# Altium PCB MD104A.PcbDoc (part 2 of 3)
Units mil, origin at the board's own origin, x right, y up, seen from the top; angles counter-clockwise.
Board outline 3684 x 4279 mil, 4 copper layers (Top Layer, GND Layer, Power Layer, Bottom Layer), stack 61.2 mil thick; 215 components, 107 nets, 500 pads, 726 vias.
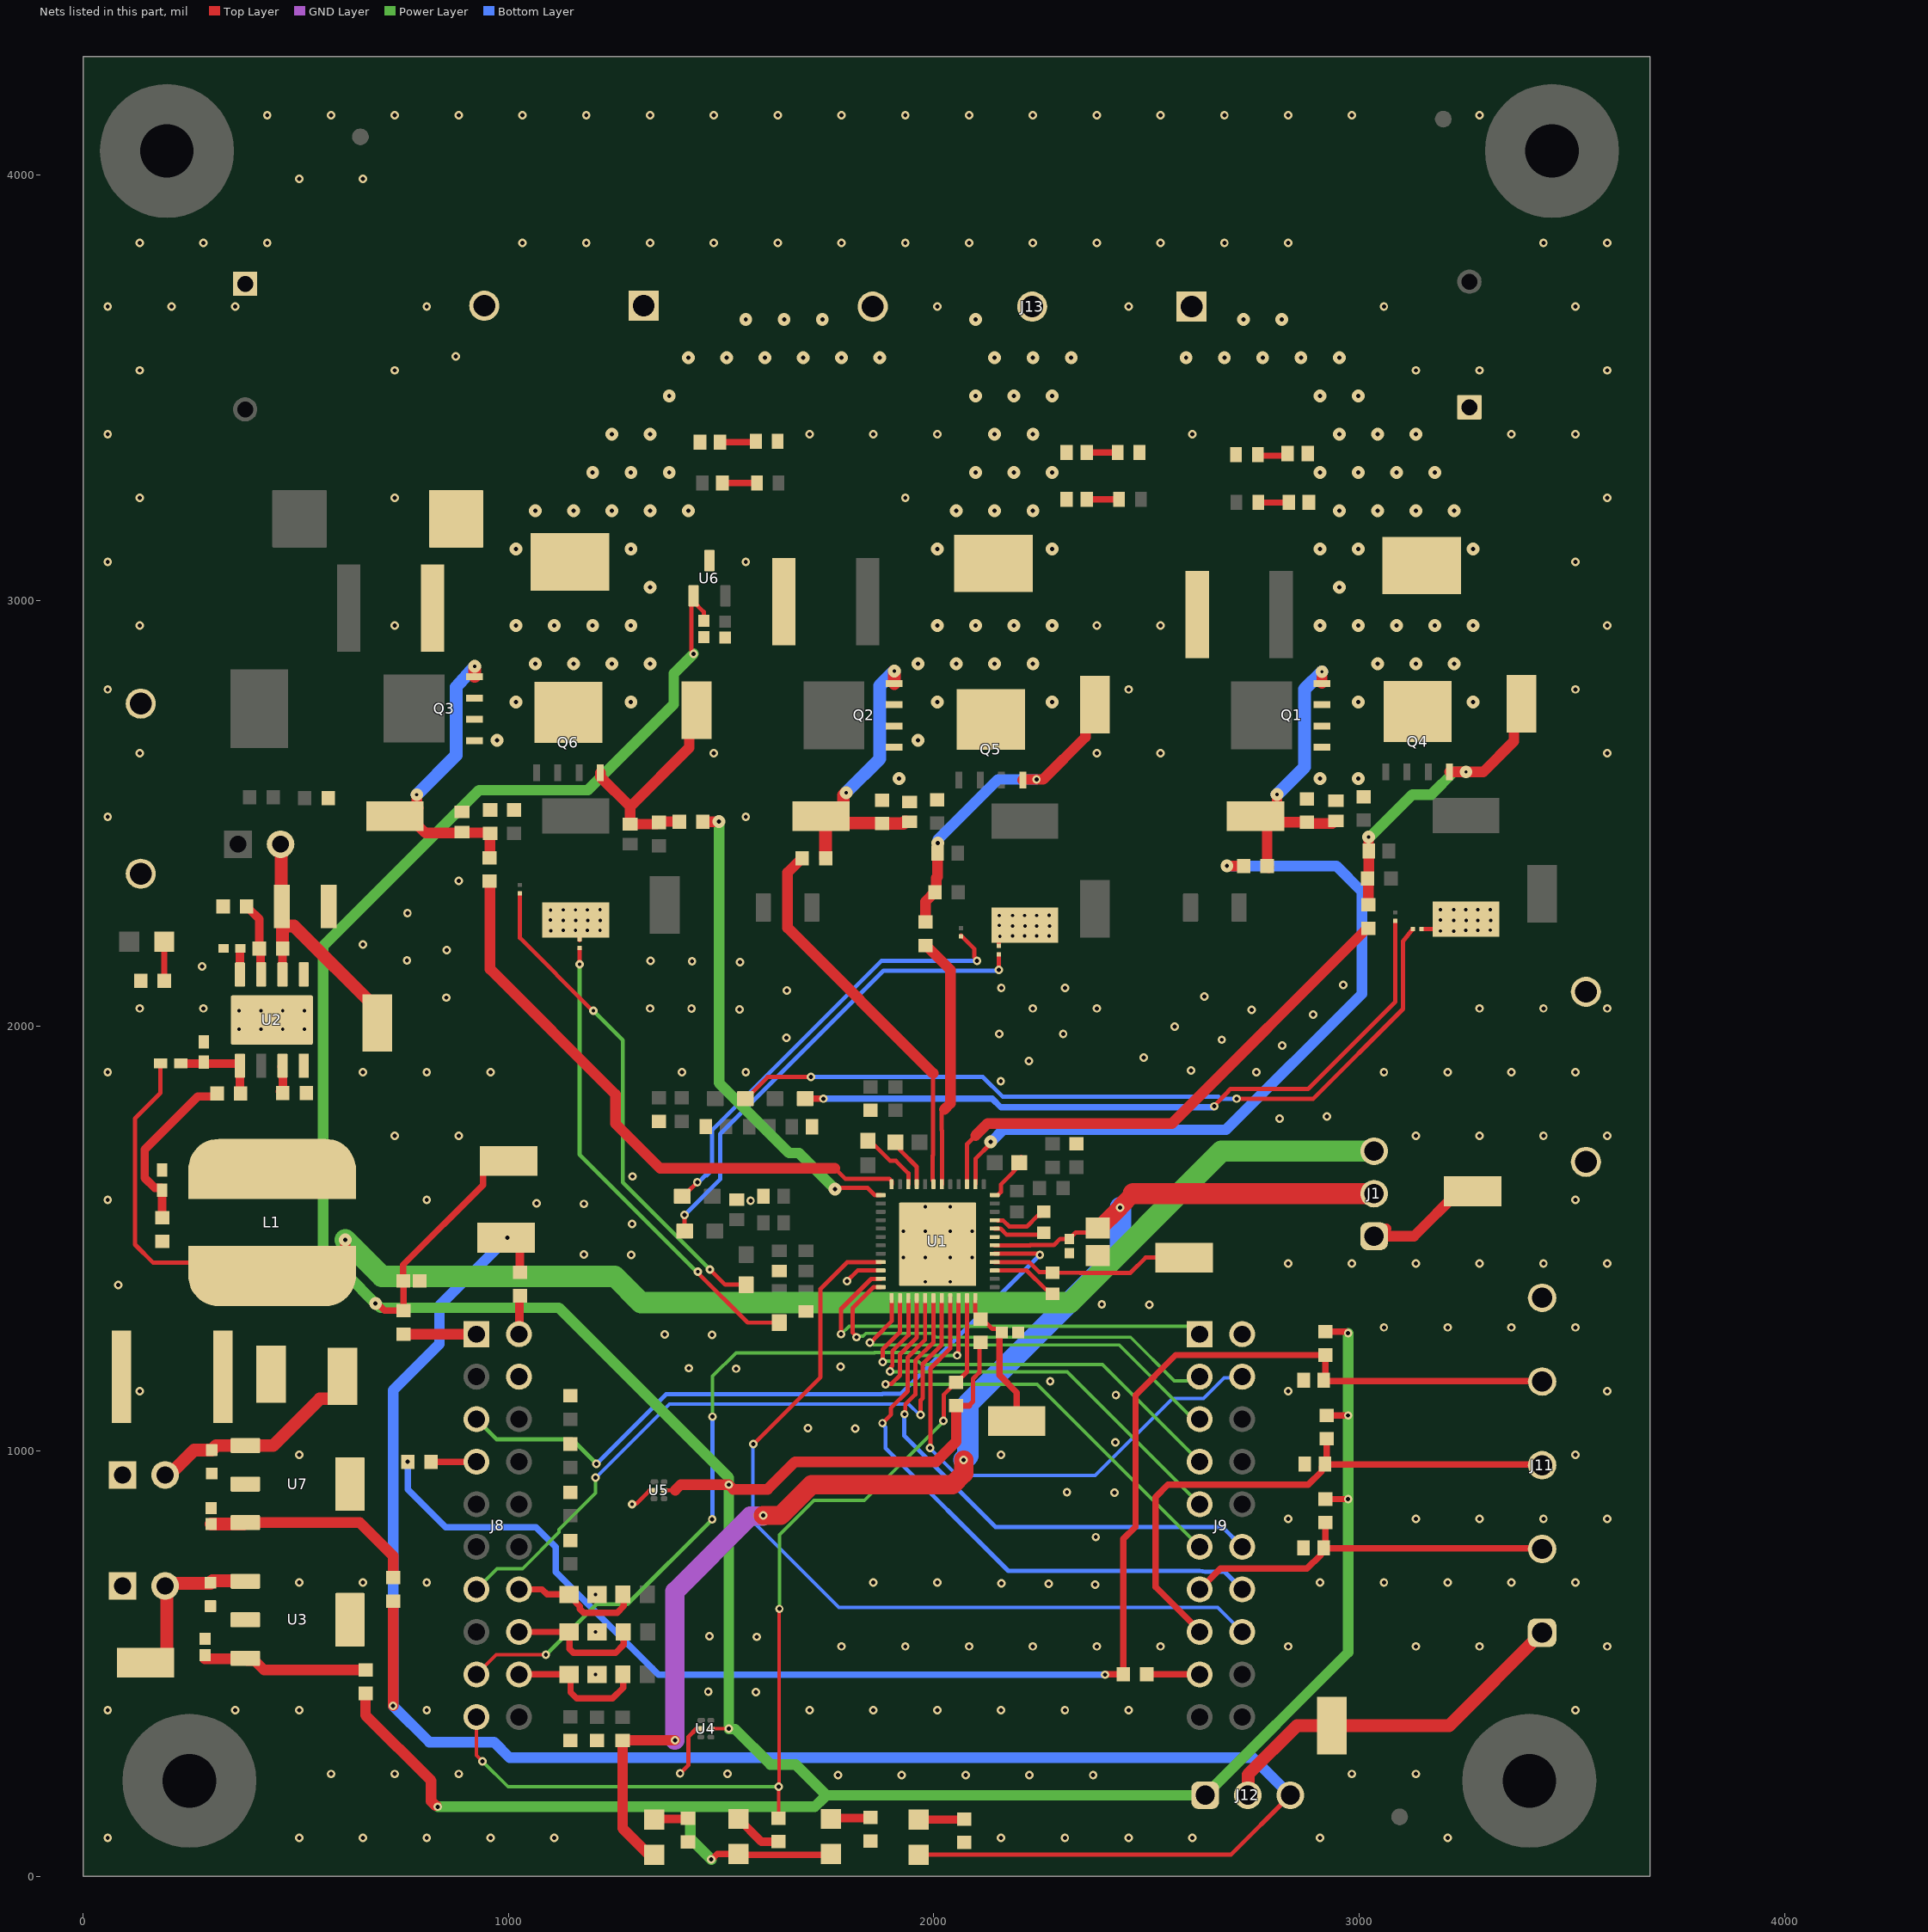
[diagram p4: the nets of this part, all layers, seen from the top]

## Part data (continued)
C10: library part CMP-06035-054272-1, "Ceramic Capacitor for Automotive 100nF ±10% 25VDC X7R 0402 Paper T/R", Capacitance=100nF, Case Code (Imperial)=0402, Case Code (Metric)=1005, Max Operating Temperature=125°C, Min Operating Temperature=-55°C, Ratings=AEC-Q200, Tolerance=10%, Voltage Rating=25V
C11 C22: library part CMP-0007085-4, "CAP, CERM, 2200 pF, 100 V, +/- 10%, X7R, AEC-Q200 Grade 1, 0603", Cap_Case=0603, Manufacturer=TDK, Supplier Part Number 1=445-5808-1-ND, TempCo=X7R, Tolerance_%=10%, Value1="0.923948 ohm", Value2=100V, ValueDisplayed=2200pF
C12 C13 C14 C15 C17 C19 C24 C25 C26 C27 C28 C29: library part CMP-03020-029902-1, "CAP CER 2200PF 100V X7R 0603", Capacitance="2,200 pF", Manufacturer=KEMET, Package=C0603C-CF, Temperature="-55°C to +125°C", Temperature Characteristic=X7R, Temperature Coefficient=30ppm/°C, Temperature Range High=+125°C, Temperature Range Low=-55°C, Tolerance=0.1, Voltage Rating="100 V"
C16 C58: library part CMP-0030960-1, "Cap Ceramic 330nF 25V X7R 10% Pad SMD 0603 +125°C Automotive T/R", Manufacturer=TDK, Operating Temperature Range="-55°C to +125°C", TempCo=0.15, Temperature Characteristic=X7R, Tolerance_%=0.1%, ValueDisplayed=330nF
C18 C20 C44: library part CMP-0064964-2, "CAP, CERM, 10 uF, 100 V,+/- 10%, X7S, AEC-Q200 Grade 1, 2220", Cap_Case=2220, Manufacturer=TDK, Supplier Part Number 1=445-8768-1-ND, TempCo=X7S, Tolerance_%=10%, Value1=Unknown, Value2=100V, ValueDisplayed=10uF
C21: library part CMP-03020-034647-1, "CAP CER 2.2UF 100V X7R 1210 AEC-Q200 C1210C225K1RACAUTO", Capacitance=2.2uF, Case Code (Imperial)=1210, Case Code (Metric)=3225, Dielectric=X7R, Dielectric Material=Ceramic, Max Operating Temperature=125°C, Min Operating Temperature=-55°C, Ratings=AEC-Q200, Tolerance=10%, Voltage Rating=100V
C23: library part CMP-0007275-4, "CAP, CERM, 56 pF, 100 V, +/- 5%, 0603, AEC-Q200", Cap_Case=0603, Manufacturer=MuRata, PartNumber=GRM1885C2A560JA01D, Supplier Part Number 1=490-1345-1-ND, TempCo=C0G/NP0, Tolerance_%=5%, Value1=Unknown, Value2=100V, ValueDisplayed=56pF
C30: library part CMP-08246-000867-1, "Cap Ceramic 47uF 25V X7R 20% Pad SMD 2220 +125°C Automotive T/R CGA9N3X7R1E476M230KB", Capacitance=47uF, Case Code (Imperial)=2220, Case Code (Metric)=5750, Max Operating Temperature=125°C, Min Operating Temperature=-55°C, Ratings=AEC-Q200, Tolerance=20%, Voltage Rating=25V
C31 C32 C51 C52 C59: library part CMP-2008-03712-2, "Ceramic Capacitor for Automotive 100nF ±10% 16VDC X7R 0402 Paper T/R GCM155R71C104KA55J", Capacitance=100nF, Case Code (Imperial)=0402, Case Code (Metric)=1005, Dielectric=X7R, Max Operating Temperature=125°C, Min Operating Temperature=-55°C, Package Quantity=1, Ratings=AEC-Q200, Tolerance=10%, Voltage Rating=16V
C33 C37 C38 C39 C40 C41 C42 C43 C45 C46 C47 C48: library part CMP-03020-019178-1, "CAP CER SMD 0603 1000PF 10% X7R C0603C102K4RACAUTO", Capacitance="1,000 pF", Manufacturer=KEMET, Package=C0603C-CF, Temperature="-55°C to +125°C", Temperature Characteristic=X7R, Temperature Coefficient=30ppm/°C, Temperature Range High=+125°C, Temperature Range Low=-55°C, Tolerance=0.1, Voltage Rating="16 V"
C34 C35: library part CMP-0120361-1, "470 µF 100 V Aluminum Electrolytic Capacitors Radial, Can 2000 Hrs @ 105°C", Digikey Part Number=399-15666-ND, Leakage Current=470uA, Manufacturer=KEMET, Mouser Part Number=80-ESH477M100AM2AA, Operating Temperature Range="-40°C to +105°C", Tolerance_%=20%, ValueDisplayed=470uF
C36 C49 C50: library part CMP-13271-000890-1, "Cap Ceramic 470pF 50V C0G ±5% Pad SMD 0603 +125°C T/R CL10C471JB81PNL", Capacitance=470pF, Case Code (Imperial)=0603, Case Code (Metric)=1608, Dielectric=C0G, Max Operating Temperature=125°C, Min Operating Temperature=-55°C, Package Quantity=15000, Ratings=AEC-Q200, Tolerance=5%, Voltage Rating=50V
C53 C54 C55 C56 C57: library part CMP-0079602-1, "CAP, CERM, 0.1 µF, 50 V,+/- 10%, X7R, AEC-Q200 Grade 1, 0603", Cap_Case=0603, Manufacturer=Kemet, Supplier Part Number 1=399-6856-1-ND, TempCo=X7R, Tolerance_%=10%, Value2=50V, ValueDisplayed=0.1µF
F1: library part CMP-0077200-3, "Fuse, 30 A, 250 VAC, 100 VDC, SMD", Irating_A=30A, Manufacturer=Littelfuse, PartNumber=0463030.ER, Supplier Part Number 1=F6439CT-ND
FID1 FID2 FID3: library part CMP-0077181-1, "Fiducial mark.  There is nothing to buy or mount.", Manufacturer=N/A
GND GND1: library part CMP-0075110-1, "1mm Uninsulated Shorting Plug, 10.16mm spacing, TH", Manufacturer=Harwin, Supplier Part Number 1=952-1873-ND
H1 H2 H3 H4: library part CMP-0003611-1, Manufacturer=Keystone, Supplier Part Number 1=36-1902E-ND
H5 H6 H7 H8: library part CMP-0003617-1, "Machine Screw, Round, #4-40 x 1/4, Nylon, Philips panhead", Manufacturer="B&F Fastener Supply", Supplier Part Number 1=H542-ND
J1 J12: library part CMP-0054796-4, "Header, 2.54 mm, 3x1, Gold, TH", Manufacturer="Wurth Elektronik", Supplier Part Number 1=732-5316-ND
J6 J7 J15: library part CMP-0054566-1, "Header, 100mil, 2x1, Gold, TH", Color=Black, Current_A=3A, Manufacturer="Sullins Connector Solutions", Supplier Part Number 1=S1011E-02-ND, Voltage_V=1.8kV
J8 J9: library part CMP-0075613-1, "Receptacle, 2.54mm, 10x2, Gold, TH", Color=Black, Current_A=6.3A, Manufacturer=Samtec, Voltage_V=550V
J10: library part CMP-0055527-1, "Terminal Block, 9.52mm, 2x1, R/A, TH", Color=Green, Current_A=32A, Manufacturer="Phoenix Contact", PartNumber=1902547, Supplier Part Number 1=277-5951-ND, Voltage_V=1kV
J11: library part CMP-0055532-1, "Terminal Block, 5mm, 5x1, R/A, TH", Color=Green, Current_A=16A, Manufacturer="Phoenix Contact", PartNumber=1792892, Supplier Part Number 1=277-2521-ND, Voltage_V=400V
J13: library part CMP-0055528-1, "Terminal Block, 9.52mm, 3x1, R/A, TH", Color=Green, Current_A=32A, Manufacturer="Phoenix Contact", PartNumber=1904150, Supplier Part Number 1=277-6184-ND, Voltage_V=1kV
L1: library part CMP-0057541-2, "Inductor, Drum Core, Ferrite, 68 uH, 1.1 A, 0.22 ohm, SMD", Manufacturer=Bourns, Supplier Part Number 1=SDR1006-680KLCT-ND, Value1="0.22 ohm", Value2=1.1A, ValueDisplayed=68uH
Logo1: library part CMP-0074844-1
Logo2: library part CMP-0074838-1, "Texas Instrument Corporate Signature"
Logo3: library part CMP-0074847-1, "FCC_disclaimer"
Logo4: library part CMP-0074769-3, Manufacturer="Texas Instruments"
LOGO5 LOGO7: library part CMP-0074837-2, "IEC 61010-1 Hot Surface Warning", Manufacturer="Texas Instruments"
LOGO6 LOGO8: library part CMP-0074835-1, "IEC 61010-1 High Voltage Warning"
MOTA MOTB MOTC VMOTOR: library part CMP-0055153-2, "Test Point, Compact, SMT", Manufacturer="Keystone Electronics", Supplier Part Number 1=36-5016TR-ND
nFAULT: library part CMP-0002829-3, "LED, Red, SMD", Color=red, Manufacturer=Lite-On, PartNumber=LTST-C170KRKT, Value1=W, Value2=2V
NT1 NT2 NT3 NT4 NT5 NT6: library part CMP-0078142-6, "Single point connection between nets.", Manufacturer=N/A
Q1 Q2 Q3 Q4 Q5 Q6: library part CMP-0001028-3, "MOSFET, N-CH, 100 V, 170 A, AEC-Q101, PowerPAK_SO-8L", Alternate Manufacturer=None, Manufacturer=Vishay-Siliconix, PartNumber=SQJ456EP-T1_GE3, Value2="42 nC"
R4 R46 R47 R48: library part CMP-0025701-4, "RES, 10 k, 5%, 0.1 W, AEC-Q200 Grade 0, 0603", Manufacturer=Vishay-Dale, Power_W=100mW, Supplier Part Number 1=541-10KGCT-ND, TempCo="200 ppm/C", Tolerance_%=5%, Value2=0.1W, Value_Code=10k0, ValueDisplayed=10k
R6 R7 R8 R9 R10 R28 R29 R30 R34 R35 R36 R37 R38 R39 R56: library part CMP-0081973-1, "RES, 0, 0%, 0.25 W, AEC-Q200 Grade 0, 0603", Manufacturer=Vishay-Dale, Power_W=250mW, Supplier Part Number 1=541-2779-1-ND, Tolerance_%=0%, Value2=0.25W, Value_Code=0
R11 R32 R45 R50 R53 R54: library part CMP-0097543-1, "10 Ohms ±0.1% 0.063W, 1/16W Chip Resistor 0603 (1608 Metric) Anti-Sulfur, Automotive AEC-Q200, Moisture Resistant Thin Film", Digikey Part Number=1712-CPF-A-0603B10RECT-ND, Manufacturer="TE Connectivity", Mouser Part Number=279-CPF-A-0603B10RE, Operating Temperature Range="-55°C to +155°C", Power_W=62.5mW, TempCo=25ppm/°C, Tolerance_%=0.1%
R12: library part CMP-0025785-4, "RES, 330, 5%, 0.1 W, AEC-Q200 Grade 0, 0603", Manufacturer=Vishay-Dale, Power_W=100mW, Supplier Part Number 1=541-330GCT-ND, TempCo="200 ppm/C", Tolerance_%=5%, Value2=0.1W, Value_Code=330R, ValueDisplayed=1.0K
R13 R58: library part CMP-0025697-4, "RES, 0, 5%, 0.1 W, AEC-Q200 Grade 0, 0603", Manufacturer=Vishay-Dale, Power_W=100mW, Supplier Part Number 1=541-0.0GCT-ND, TempCo="200 ppm/C", Tolerance_%=5%, Value2=0.1W, Value_Code=0000, ValueDisplayed=0
R14 R15: library part CMP-0025785-4, "RES, 330, 5%, 0.1 W, AEC-Q200 Grade 0, 0603", Manufacturer=Vishay-Dale, Power_W=100mW, Supplier Part Number 1=541-330GCT-ND, TempCo="200 ppm/C", Tolerance_%=5%, Value2=0.1W, Value_Code=330R, ValueDisplayed=330
R16 R17: library part CMP-0022458-4, "RES, 4.99 k, 1%, 0.1 W, AEC-Q200 Grade 0, 0603", Manufacturer=Vishay-Dale, Power_W=100mW, Supplier Part Number 1=541-4.99KHCT-ND, TempCo="100 ppm/C", Tolerance_%=1%, Value2=0.1W, Value_Code=4k99, ValueDisplayed=4.99k
R19: library part CMP-0025736-4, "RES, 1.0 M, 5%, 0.1 W, AEC-Q200 Grade 0, 0603", Manufacturer=Vishay-Dale, Power_W=100mW, Supplier Part Number 1=541-1.0MGCT-ND, TempCo="200 ppm/C", Tolerance_%=5%, Value2=0.1W, Value_Code=1M00, ValueDisplayed=1.0M
R20: library part CMP-0026702-1, "RES, 681k, 1%, 0.1 W, AEC-Q200 Grade 0, 0402", Manufacturer=Panasonic, PartNumber=ERJ-2RKF6813X, Power_W=100mW, Supplier Part Number 1=P49.9KLCT-ND, TempCo="100 ppm/C", Tolerance_%=1%, Value2=0.1W, Value_Code=681k
R21: library part CMP-0026702-1, "RES, 453 k 1%, 0.1 W, AEC-Q200 Grade 0, 0402", Manufacturer=Panasonic, Power_W=100mW, Supplier Part Number 1=P453KLCT-ND, TempCo="100 ppm/C", Tolerance_%=1%, Value2=0.1W, Value_Code=453k
R22 R60 R75 R76 R77 R78: library part CMP-0021990-4, "RES, 100 k, 1%, 0.1 W, AEC-Q200 Grade 0, 0603", Manufacturer=Vishay-Dale, Power_W=100mW, Supplier Part Number 1=541-100KHCT-ND, TempCo="100 ppm/C", Tolerance_%=1%, Value2=0.1W, Value_Code=100k
R23: library part CMP-0025950-3, "RES, 100 k, 1%, 0.063 W, AEC-Q200 Grade 0, 0402", Manufacturer=Vishay-Dale, Power_W=63mW, Supplier Part Number 1=541-100KLCT-ND, TempCo="100 ppm/C", Tolerance_%=1%, Value2=0.063W, Value_Code=100k
R24: library part CMP-0026702-1, "RES, 49.9 k, 1%, 0.1 W, AEC-Q200 Grade 0, 0402", Manufacturer=Panasonic, Power_W=100mW, Supplier Part Number 1=P49.9KLCT-ND, TempCo="100 ppm/C", Tolerance_%=1%, Value2=0.1W, Value_Code=49k9, ValueDisplayed=49.9k
R25 R26 R27 R40 R41 R42: library part CMP-2000-01928-1, "2.7, 0.125W, 0603, AEC-Q200", Manufacturer="KOA Speer", Part Number=RK73B1JTTD2R7J
R31 R33 R51: library part CMP-0015751-2, "RES, 0.005, 1%, 3 W, AEC-Q200 Grade 0, 2512", Manufacturer=Bourns, Power_W=3W, Supplier Part Number 1=CRE2512-FZ-R005E-3CT-ND, TempCo="75 ppm/C", Tolerance_%=1%, Value_Code=5L000, ValueDisplayed=0.005
R43 R44: library part CMP-0094724-1, "Jumper 0.25W, 1/4W Chip Resistor 1206 (3216 Metric) - Thick Film", Digikey Part Number=541-4170-1-ND, Manufacturer=Vishay, Mouser Part Number=71-CRCW12060000Z0EAC, Operating Temperature Range="-55°C to +155°C", Power_W=250mW
R49 R59 R63: library part CMP-2000-00728-1, "160, 0.1W, 0603, AEC-Q200 ERJ-3GEYJ161V", Manufacturer=Panasonic, Part Number=ERJ-3GEYJ161V
R52 R55 R65 R74 R86: library part CMP-0022663-4, "RES, 97.6 k, 1%, 0.1 W, AEC-Q200 Grade 0, 0603", Manufacturer=Vishay-Dale, Power_W=100mW, Supplier Part Number 1=541-97.6KHCT-ND, TempCo="100 ppm/C", Tolerance_%=1%, Value2=0.1W, Value_Code=97k6, ValueDisplayed=97.6k
R57: library part CMP-0025784-4, "RES, 330 k, 5%, 0.1 W, AEC-Q200 Grade 0, 0603", Manufacturer=Vishay-Dale, Power_W=100mW, Supplier Part Number 1=541-330KGCT-ND, TempCo="200 ppm/C", Tolerance_%=5%, Value2=0.1W, Value_Code=330k
R66 R80 R81 R82 R91: library part CMP-0022371-4, "RES, 3.01 k, 1%, 0.1 W, AEC-Q200 Grade 0, 0603", Manufacturer=Vishay-Dale, Power_W=100mW, Supplier Part Number 1=541-3.01KHCT-ND, TempCo="100 ppm/C", Tolerance_%=1%, Value2=0.1W, Value_Code=3k01, ValueDisplayed=3.01k
SH-J1 SH-J2 SH-J3 SH-J4 SH-J5: library part CMP-0003623-3, "Shunt, 100mil, Gold plated, Black", Alternate Manufacturer=3M, Alternate PartNumber=969102-0000-DA, Manufacturer=Samtec, Supplier Part Number 1=SAM8858-ND
U1: library part CMP-0122985-1, "48V Battery Three-Phase Smart Gate Driver with Accurate Current Sensing and Advanced Monitoring", Manufacturer="Texas Instruments", Max Supply Voltage=85V, Min Supply Voltage=8V, Operating Temperature Range="-40°C to +150°C"
U2: library part CMP-0080798-1, "100-V Low IQ Synchronous Buck Regulator, DDA0008E (SOIC-8)", Alternate Manufacturer="Texas Instruments"
U3: library part CMP-0080825-1, "500-mA, 25-V, Linear Voltage Regulators, DCY0004A (SOT-223-4)", Alternate Manufacturer="Texas Instruments", Alternate PartNumber=UA78M33CDCY
U4 U5: library part CMP-0043120-3, "4-Channel ESD Solution for High-Speed Differential Interface, DRY0006A (USON-6)", Breakdown Voltage(Min)(V)=9, Differential Capacitance(pF)=0.05, IO Capacitance(Typ)(pF)=0.8, IO Leakage Current(nA)=Jan-00, Manufacturer="Texas Instruments", Operating Temperature Range="-40 to 85 C", Rating=Catalog
U6: library part CMP-0088337-2, "Temperature Sensor Analog, Local -40°C ~ 150°C 10mV/°C SOT-23-3", Digikey Part Number=296-TMP235A2DBZRCT-ND, Manufacturer="Texas Instruments", Max Supply Voltage=5.5V, Min Supply Voltage=2.3V, Mouser Part Number=595-TMP235A2DBZR, Operating Supply Current=9uA, Operating Temperature Range="-40°C to +150°C"
U7: library part CMP-0080822-1, "500-mA, 25-V, Linear Voltage Regulators, DCY0004A (SOT-223-4)", Alternate Manufacturer="Texas Instruments", Alternate PartNumber=UA78M05CDCY
ZZ1: library part CMP-0003616-3
ZZ2: library part CMP-0077236-1
ZZ3: library part CMP-0077237-1
ZZ4: library part CMP-0077238-1

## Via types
v1: diameter 20/20/20/20 (per signal layer), hole 10, Top Layer to Bottom Layer, tented both sides, 247 vias
v2: diameter 20, hole 10, Top Layer to Bottom Layer, tented both sides, 197 vias
v3: diameter 30, hole 10, Top Layer to Bottom Layer, tented both sides, 161 vias
v4: diameter 20, hole 7.87, Top Layer to Bottom Layer, tented both sides, 56 vias
v5: diameter 30/30/30/30 (per signal layer), hole 10, Top Layer to Bottom Layer, tented both sides, 36 vias
v6: diameter 19.68, hole 7.87, Top Layer to Bottom Layer, tented both sides, 16 vias
v7: diameter 30, hole 7.87, Top Layer to Bottom Layer, tented both sides, 8 vias
v8: diameter 19.68, hole 7.87, Top Layer to Bottom Layer, 4 vias
v9: diameter 20, hole 8, Top Layer to Bottom Layer, tented both sides, 1 vias

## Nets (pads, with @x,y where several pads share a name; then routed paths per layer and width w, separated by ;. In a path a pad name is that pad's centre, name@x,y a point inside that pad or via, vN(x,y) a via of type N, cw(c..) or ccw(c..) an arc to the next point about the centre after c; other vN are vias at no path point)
3.3V: 3.3V.1 C9.1 C51.1 J12.1 nFAULT.1 R4.1 R6.1 R9.1 R46.1 R47.1 R48.1 R58.2 TP_3.3V.1 U4.5 U5.5 U6.1 | length 9797.9
  Top Layer w8: U4.5@1475.81,347.26 v2(1518.01,347.26)
  Top Layer w10: C9.1@752.75,1399.88 C9.1@753.44,1399.18 ; TP_3.3V.1@971.79,1653.83 TP_3.3V.1@1000.26,1682.3 ; U5.5@1365.81,907.88 1391.93,907.88 ; v2(1435.11,2874.62) 1435.11,2877.33 1430.03,2882.41 1430.03,3005.74 U6.1@1435.11,3010.82 1435.11,2997.04 1459.02,2973.14 C51.1@1459.02,2952.59 ; 2082.14,1106.48 2092.27,1116.61 2092.27,1170.03 2106.99,1184.76 R9.1@2106.99,1251.34
  Top Layer w15: v3(687.61,1347.23) 691.67,1347.23 708.9,1330 R6.1@753.44,1330 C9.1@753.44,1399.18 ; C9.1@752.75,1399.88 752.75,1437.96 940.26,1625.47 940.26,1654.8 967.76,1682.3 TP_3.3V.1@1000.26,1682.3 ; v2@830.15,166.38 832.5,164.02 v2@832.5,162.38 ; v2(1476.81,39.88) 1478.16,39.88 1490.83,52.54 nFAULT.1@1541,52.54 1542.9,50.64 1756.52,50.64 3.3V.1@1758.43,52.54 ; R4.1@2052.61,1106.85 2052.61,1106.48 2082.14,1106.48 ; R46.1@2920.34,887.11 v2(2973.94,887.11) ; R48.1@2920.34,1280.81 2968.78,1280.81 2972.59,1277.01 v2(2973.94,1277.01) ; R47.1@2923.14,1083.96 2923.26,1083.84 2973.82,1083.84 v2(2973.94,1083.72)
  Top Layer w25: R58.2@664,430.32 664,379.09 818.22,224.88 818.22,176.66 828.5,166.38 v2@830.15,166.38 ; 1391.93,907.88 1405.06,921.01 v2(1517.88,921.01) 1528.63,910.26 1609.34,910.26 1673.95,974.88 2005.22,974.88 2052.61,1022.27 R4.1@2052.61,1106.48
  Power Layer w15: v2(1435.11,2874.62) v2@1435.11,2875.98 ; v2(1518.01,347.26) v2@1518.96,346.3
  Power Layer w25: v2(834,163.88) 1427.21,163.88 ; v2(1435.11,2874.62) 1388.52,2828.04 1388.52,2755.8 1186.67,2553.95 931.07,2553.95 564,2186.88 564,1468.88 618.31,1414.57 620.26,1414.57 688.57,1346.27 689.92,1346.27 699.3,1336.89 1118.44,1336.89 1517.88,937.45 v2(1517.88,921.01) ; v2(1476.81,39.88) 1427.21,89.48 1427.21,163.88 ; v2(1518.01,347.26) v2@1518.01,920.89 ; v2@1518.96,346.3 1532.62,346.3 1615.79,263.13 1674.88,263.13 1747.14,190.88 ; v2(2973.94,1277.01) v2(2973.94,1083.72) v2(2973.94,887.11) 2973.94,526.82 J12.1@2638,190.88 1747.14,190.88 ; 1427.21,163.88 1720.14,163.88 1740.31,184.05 1747.14,190.88
5V: 5V.1 J12.3 R7.2 R13.2 TP_5V.1 | length 4680.7
  Top Layer w10: TP_5V.1@994.49,1501.72 997,1501.72 TP_5V.1@1027,1471.72 ; 5V.1@1963.94,51.03 2698.15,51.03 J12.3@2838,190.88
  Top Layer w20: R7.2@1027,1420.44 TP_5V.1@1027,1471.72
  Top Layer w25: v2(729,400.88) R13.2@729,645.2
  Bottom Layer w25: v3(997.93,1501.72) 837.84,1341.62 837.84,1251.71 729,1142.88 v2(729,400.88) 814.04,315.84 966.04,315.84 1003,278.88 2750,278.88 J12.3@2838,190.88
BSTA: C6.1 U1.36 | length 122.7
  Top Layer w8: U1.36@2142.94,1601.88 2150.02,1601.88 U1.36@2150.75,1602.61
  Top Layer w10: U1.36@2150.75,1602.61 2157.41,1609.27 2157.41,1626.67 2186.74,1656.01 2186.74,1656.92 2199.69,1669.88 C6.1@2200.61,1669.88 ; C6.1@2186.74,1672.92 2205.05,1691.23 C6.1@2205.05,1691.43
BSTB: C7.1 U1.45 | length 120.7
  Top Layer w10: C7.1@1906.22,1725.42 1907.13,1725.42 1920.09,1712.47 1920.09,1708.26 1959.79,1668.56 1959.79,1627.55 U1.45@1959.87,1627.48
BSTC: C8.1 U1.46 | length 151.3
  Top Layer w10: C8.1@1837.24,1716 C8.1@1841.61,1716 ; C8.1@1851,1729.49 1851,1728.57 1897.27,1682.3 1910.84,1682.3 1940.18,1652.96 U1.46@1940.18,1627.48
BUCK_OUT: BUCK_TP.1 C22.1 C30.1 J1.3 J7.1 J15.1 L1.2 R21.2 | length 3467.3
  Top Layer w10: R21.2@182.21,1911.41 182.21,1842.27 122.13,1782.19 122.13,1485.61 164.84,1442.9 263.02,1442.9 L1.2@287.04,1442.9 ; BUCK_TP.1@436.16,1174.88 BUCK_TP.1@442.04,1180.76 ; L1.2@566.17,1411.41 L1.2@570.75,1411.41
  Top Layer w20: L1.2@602,1442.9 L1.2@611.13,1452.03
  Top Layer w25: L1.2@263.02,1442.9 L1.2@294.52,1411.41 ; L1.2@566.17,1411.41 L1.2@599.83,1445.07 ; L1.2@586.24,1458.66 L1.2@602,1458.66 ; L1.2@602,1442.9 599.32,1442.9 597.28,1444.94 597.28,1458.66 605.31,1458.66 616.42,1469.77 v3(616.42,1496.73)
  Top Layer w30: J7.1@95,684.88 J7.1@97,682.88
  Power Layer w50: v3(616.42,1496.73) 702.27,1410.88 1249.88,1410.88 1311.88,1348.88 2320.15,1348.88 2676.48,1705.21 J1.3@3035.04,1705.21
CPTH: C3.1 U1.33 | length 128.7
  Top Layer w10: U1.33@2149.75,1542.55 2162.7,1542.55 2177.22,1528.04 2218.66,1528.04 2243.51,1552.88 2251.38,1552.88 2253.44,1554.95 C3.1@2253.44,1562.82
CPTL: C3.2 U1.32 | length 126.4
  Top Layer w10: U1.32@2142.94,1523.14 2156.83,1523.14 2171.37,1508.61 2256.45,1508.61 C3.2@2261.31,1513.47
DRVOFF: J9.16 U1.9 | length 2038.5
  Top Layer w10: v2(1575.95,1016.35) 1733.52,1173.93 1733.52,1381.4 1796.25,1444.13 1874.94,1444.13 U1.9@1875.22,1444.4
  Bottom Layer w8: v2(1575.95,1016.35) 1574.45,1014.86 1574.45,834.8 1776.76,632.49 2667.39,632.49 J9.16@2725,574.88
DVDD: C1.1 DVDD.1 U1.28 | length 470.7
  Top Layer w10: U1.28@2142.94,1444.4 2224.2,1444.4 2247.96,1420.65 2276.54,1420.65 2277.9,1419.29 C1.1@2278.95,1419.29 2343.24,1419.29 2343.33,1419.2 2462.08,1419.2 2497.75,1454.88 DVDD.1@2588.38,1454.88
EBRAKE: J8.5 U1.29 | length 1678.9
  Top Layer w10: U1.29@2142.94,1464.09 2243.82,1464.09 2246.62,1461.29 v2(2249.32,1461.29)
  Power Layer w10: J8.5@925,1074.88 971.91,1027.97 1148.96,1027.97 v2(1207.02,969.91)
  Bottom Layer w10: v2(1207.02,969.91) 1370.82,1133.71 1879.32,1133.71 1880.03,1134.41 1922.44,1134.41 v2(2249.32,1461.29)
GHA: R28.1 U1.38 | length 1754
  Top Layer w10: U1.38@2097.66,1627.48 2097.94,1627.75 2097.94,1687.46 2133.64,1723.17 v3(2133.64,1727.39)
  Top Layer w25: v3(2689,2375.88) R28.1@2728.44,2375.88
  Bottom Layer w25: v3(2133.64,1727.39) 2135,1727.39 2163.01,1755.4 2686.82,1755.4 3006.36,2074.94 3006.36,2315.72 2946.2,2375.88 v3(2689,2375.88)
GHB: R29.1 U1.43 | length 923.2
  Top Layer w10: 1998.36,1888.09 1998.36,1695.38 1997.42,1694.45 1997.42,1635.82 1999.24,1634.01 U1.43@1999.24,1627.48
  Top Layer w25: R29.1@1687.19,2393.94 1687.19,2389.71 1685.58,2389.71 1656.16,2360.29 1656.16,2230.29 1998.36,1888.09
GHC: R30.1 U1.48 | length 1404.6
  Top Layer w10: 1767.27,1664.84 1791.59,1640.52 1894.95,1640.52 1900.81,1634.66 U1.48@1900.81,1627.48
  Top Layer w25: R30.1@956.91,2340 956.91,2133.26 1251.67,1838.49 1251.67,1769.76 1356.58,1664.84 1767.27,1664.84
GLA: R34.1 U1.39 | length 1239.3
  Top Layer w10: U1.39@2077.98,1627.48 2078.25,1627.75 2078.25,1722.02 2098.27,1742.04
  Top Layer w25: 2098.27,1742.04 2126.54,1770.31 2559.87,1770.31 R34.1@3014.55,2224.99
GLB: R35.1 U1.42 | length 594.8
  Top Layer w10: U1.42@2018.92,1627.48 2018.92,1753.83 2018.68,1754.07 2018.68,1797.11 2024.61,1803.04
  Top Layer w25: R35.1@1980.44,2188.89 1981.43,2188.89 2039.1,2131.22 2039.1,1817.53 2024.61,1803.04
GLC: R36.1 U1.1 | length 1143.9
  Top Layer w10: v3(1767.91,1616.12) 1770.5,1618.71 1844.58,1618.71 1861.41,1601.88 U1.1@1875.22,1601.88
  Top Layer w25: R36.1@1456.91,2480.03 1456.99,2479.95 1494.93,2479.95 v3(1495,2479.88)
  Power Layer w25: v3(1495,2479.88) 1495,1865.74 1659.79,1700.95 1683.09,1700.95 v3(1767.91,1616.12)
GND: C1.2 C5.2 C9.2 C10.2 C16.1 C18.2 C20.2 C21.2 C30.2 C31.2 C32.2 C34.1 C35.1 C36.2 C37.2 C38.2 C39.2 C40.2 C41.2 C44.2 C45.2 C46.2 C47.2 C48.2 C49.2 C50.2 C51.2 C52.2 C53.1 C54.1 C55.1 C56.1 C57.1 C58.1 C59.2 GND1.1 GND1.2 GND.1 GND.2 J8.4 J9.2 J10.2 J11.5 NT1.2 NT2.2 NT3.2 R12.1 R15.1 R16.1 R17.1 R23.1 R24.1 R31.1 R33.1 R40.1 R41.1 R42.1 R51.1 R57.1 R66.1 R80.1 R81.1 R82.1 R91.1 U1.10 U1.27 U1.49 U2.1 U2.9@443.83,2013.41 U3.2 U3.4 U4.2 U5.2 U6.3 U7.2 U7.4 | length 629.2
  Top Layer w10: v4(1099,2271.88) 1102.68,2271.88 1125.73,2248.83 R51.1@1158,2248.83 1167,2239.83 NT3.2@1167,2200.75 ; v9(1290.29,874.88) 1292.21,876.79 1301.12,876.79 1331.3,906.97 1341.28,906.97 U5.2@1342.19,907.88 ; v1(1403.41,242.02) 1423.31,261.92 1423.31,328.36 1441.3,346.35 1451.28,346.35 U4.2@1452.19,347.26 ; v1(1796.1,1399.94) 1820.88,1424.72 U1.10@1875.22,1424.72 ; U1.27@2142.94,1424.72 2218.61,1424.72 2263.45,1379.88 2267.96,1379.88 C1.2@2269.71,1378.13 ; NT2.2@2153,2187.88 2153,2208.33 v4(2155.27,2210.6) ; R33.1@2188.89,2236.54 R33.1@2195.16,2236.54 ; NT1.2@3146.46,2227.88 3186,2227.88 v4(3191,2222.88)
  other v1: 58,90.88 508,90.88 658,90.88 808,90.88 958,90.88 1108,90.88 2158,90.88 2308,90.88 2458,90.88 2608,90.88 2908,90.88 3208,90.88 1774.59,238.18 1924.59,238.18 2074.59,238.18 2224.59,238.18 2374.59,238.18 583,240.88 733,240.88 883,240.88 1514.83,240.89 2983,240.88 3133,240.88 58,390.88 358,390.88 508,390.88 808,390.88 1708,390.88 1858,390.88 2008,390.88 2158,390.88 2308,390.88 2458,390.88 3508,390.88 1581.37,433.01 1469.95,434.14 1783,540.88 1933,540.88 2083,540.88 2233,540.88 2383,540.88 2533,540.88 2833,540.88 3133,540.88 3283,540.88 3583,540.88 1584.12,563.26 1472.7,564.39 2379.55,686.39 2270.36,687.72 2158.94,688.84 508,690.88 658,690.88 808,690.88 1858,690.88 2008,690.88 2908,690.88 3058,690.88 3208,690.88 3358,690.88 3508,690.88 2380.67,797.81 2833,840.88 3133,840.88 3283,840.88 3433,840.88 3583,840.88 2424.38,902.46 2312.96,903.58 508,990.88 2158,990.88 3508,990.88 2427.02,1020.67 1815.56,1053.04 1704.14,1054.17 2428.14,1132.09 133,1140.88 2833,1140.88 3583,1140.88 2273.62,1164.35 1535.24,1193.84 1423.82,1194.97 1780.49,1198.2 1478.78,1272.91 1367.36,1274.03 3058,1290.88 3208,1290.88 3358,1290.88 3508,1290.88 2506.31,1344.31 2394.89,1345.44 82.51,1390.15 2833,1440.88 2983,1440.88 3133,1440.88 3283,1440.88 3433,1440.88 3583,1440.88 1288.59,1461.06 1177.17,1462.18 1290.67,1534.34 1177.28,1581.11 1065.86,1582.24 58,1590.88 808,1590.88 3508,1590.88 1291.8,1645.76 733,1740.88 883,1740.88 3133,1740.88 3283,1740.88 3433,1740.88 3583,1740.88 2812.46,1781.36 2923.7,1786.69 2157.35,1869.8 58,1890.88 658,1890.88 808,1890.88 958,1890.88 1408,1890.88 1558,1890.88 2758,1890.88 3058,1890.88 3208,1890.88 3358,1890.88 3508,1890.88 2604.25,1894.63 2223.41,1917.13 2493.27,1925.47 2819.09,1953.39 2676.82,1967.2 1653.14,1971.48 2153.96,1980.57 2303.96,1980.57 2565.84,1998.04 2891.66,2025.96 1543.35,2038.23 2747.29,2037.67 1430.49,2040.35 133,2040.88 283,2040.88 1333,2040.88 2233,2040.88 2383,2040.88 3283,2040.88 3433,2040.88 3583,2040.88 853.67,2066.25 2636.31,2068.51 1654.26,2082.9 2158.45,2089.16 2308.45,2089.16 2962.12,2096.42 279.72,2139.79 1544.48,2149.65 1334.13,2152.3 1431.62,2151.77 761.42,2153.3 854.79,2177.67 658,2190.88 762.54,2264.72 883,2340.88 58,2490.88 1558,2490.88 133,2640.88 1483,2640.88 2383,2640.88 2533,2640.88 3583,2640.88 58,2790.88 2458,2790.88 3508,2790.88 133,2940.88 733,2940.88 2383,2940.88 2533,2940.88 3583,2940.88 58,3090.88 1558,3090.88 3508,3090.88 133,3240.88 733,3240.88 1933,3240.88 3583,3240.88 58,3390.88 1708,3390.88 1858,3390.88 2008,3390.88 2608,3390.88 3358,3390.88 3508,3390.88 133,3540.88 733,3540.88 3133,3540.88 3283,3540.88 3583,3540.88 876.35,3573.88 58,3690.88 208,3690.88 358,3690.88 808,3690.88 2008,3690.88 2458,3690.88 3058,3690.88 3508,3690.88 133,3840.88 283,3840.88 433,3840.88 1033,3840.88 1183,3840.88 1333,3840.88 1483,3840.88 1633,3840.88 1783,3840.88 1933,3840.88 2083,3840.88 2233,3840.88 2383,3840.88 2533,3840.88 2683,3840.88 2833,3840.88 3433,3840.88 3583,3840.88 508,3990.88 658,3990.88 433,4140.88 583,4140.88 733,4140.88 883,4140.88 1033,4140.88 1183,4140.88 1333,4140.88 1483,4140.88 1633,4140.88 1783,4140.88 1933,4140.88 2083,4140.88 2233,4140.88 2383,4140.88 2533,4140.88 2683,4140.88 2833,4140.88 2983,4140.88 3283,4140.88
  other v2: 1569.13,1588.49
  other v4: 1205.06,474.88 1205.06,574.88 1205.06,662.94 2185.18,2211.15 2213.79,2211.15 2241.69,2211.15 2271.31,2211.5 3222.2,2222.72 1099.27,2223.77 1129.18,2224.32 1157.77,2224.32 1185.69,2224.32 1215.31,2224.67 3250.79,2224.5 3278.69,2224.5 3308.31,2224.85 2185.12,2234.6 2214.12,2234.6 2242.12,2234.6 2272.12,2234.6 2154.19,2236.13 1129.12,2247.77 1158.2,2247.77 1186.12,2247.77 1216.12,2247.77 3222.12,2247.95 3251.12,2247.95 3279.12,2247.95 3309.12,2247.95 1098.94,2248.56 3191.2,2248.72 2154.19,2259.26 2185.18,2259.26 2213.79,2259.26 2241.69,2259.26 2271.31,2259.6 1129.18,2272.43 1157.79,2272.43 1185.69,2272.43 1215.31,2272.77 3191.19,2272.6 3222.18,2272.6 3250.79,2272.6 3278.69,2272.6 3308.31,2272.95
  other v6: 1979.94,1398.18 2038.21,1398.18 1928.37,1455.27 1979.94,1455.27 2038.21,1455.27 2089.79,1455.27 1928.37,1517.16 1979.94,1517.16 2038.21,1517.16 2089.79,1517.16 1979.94,1574.25 2038.21,1574.25 367.06,1991.75 520.6,1991.75 367.06,2035.06 520.6,2035.06
  other v8: 418.24,1991.75 469.42,1991.75 418.24,2035.06 469.42,2035.06
GVDD: C5.1 C10.1 GVDD.1 J1.2 R86.2 U1.30 | length 3259.6
  Top Layer w10: R86.2@1268.33,319.3 R86.2@1269.21,320.18 ; U1.30@2142.94,1483.77 2226.44,1483.77 2226.83,1484.17 2282.19,1484.17 2296.86,1498.84 C10.1@2318.6,1498.84 2318.6,1499.68 2324.87,1505.95 2325.71,1505.95 2333.76,1513.99 C5.1@2369.63,1513.99
  Top Layer w25: R86.2@1268.33,319.3 1268.33,113.21 GVDD.1@1329,52.54 ; R86.2@1269.21,320.18 v2(1391.4,320.18)
  Top Layer w40: C5.1@2387.54,1522.16 v2(2438.2,1572.82) 2438.2,1574.04 2469.36,1605.21
  Top Layer w45: v2(1599.13,848.75) 1640.29,848.75 1712.41,920.88 2043.82,920.88 2070.18,947.24 v2(2070.18,979.2)
  Top Layer w50: 2469.36,1605.21 J1.2@3035.04,1605.21
  GND Layer w10: v2@1597.69,847.32 v2(1599.13,848.75)
  GND Layer w45: v2(1391.4,320.18) 1391.4,670.12 1568.6,847.32 v2@1597.69,847.32
  Bottom Layer w50: v2(2070.18,979.2) 2080,989.02 2080,1110.69 2438.68,1469.37 2438.68,1572.34 v2(2438.2,1572.82)
GVDD_EXT: GVDD_EXT.1 J1.1 | length 311.3
  Top Layer w25: J1.1@3063.59,1522.88 3052.71,1522.88 J1.1@3035.04,1505.21 3128.59,1505.21 3234.21,1610.83 GVDD_EXT.1@3266.71,1610.83
HALL_A: C39.1 J9.13 J11.2 R46.2 | length 908.8
  Top Layer w15: J9.13@2625,674.88 2673.71,723.59 2877.11,723.59 2909.14,755.62 2909.14,765.46 C39.1@2916.41,772.73 ; R46.2@2921.33,831.99 R46.2@2920.34,831.99 2920.34,772.73 2921.77,771.3 3428.58,771.3 J11.2@3430,769.88
HALL_B: C38.1 J9.15 J11.3 R47.2 | length 1363.5
  Top Layer w15: J9.15@2625,574.88 2625,576.88 2521,680.88 2521,891.88 2550,920.88 2880.35,920.88 2911.94,952.47 2911.94,962.31 C38.1@2919.21,969.58 ; R47.2@2923.14,1028.84 2923.14,969.58 2924.57,968.15 3428.58,968.15 J11.3@3430,966.73
HALL_C: C37.1 J11.4 R8.1 R10.1 R48.2 | length 3686.3
  Top Layer w15: v2(2402.05,474.29) 2402.64,474.88 R10.1@2445.44,474.88 2445.44,793.46 2474.22,822.24 2474.22,1131.59 2568.32,1225.69 R48.2@2920.34,1225.69 2920.5,1225.53 2920.5,1166.59 2920.66,1166.43 2922.08,1165 3428.58,1165 J11.4@3430,1163.58
  Bottom Layer w15: v2(763.1,974.88) 763.1,909.94 852.27,820.76 1064.86,820.76 1111.39,774.23 1111.39,715.57 1353.09,473.88 1566.23,473.88 1566.64,474.29 v2(2402.05,474.29)
HALL_PWR: HALL_EXT.1 J11.1 J12.2 | length 878.3
  Top Layer w30: J12.2@2738,190.88 2738.86,191.74 2738.86,239.59 2853.72,354.45 HALL_EXT.1@2935.94,354.45 3211.42,354.45 J11.1@3430,573.03
INHA: J9.1 U1.11 | length 1040.5
  Top Layer w10: v2(1781.77,1274.88) 1781.77,1333.95 1852.58,1404.76 1874.94,1404.76 U1.11@1875.22,1405.03
  Power Layer w8: v2(1781.77,1274.88) 1782.13,1274.88 1800.62,1293.37 2606.51,1293.37 J9.1@2625,1274.88
INHB: J9.5 U1.13 | length 971.7
  Top Layer w10: v2(1849.52,1254.91) 1850.81,1253.63 1851.37,1253.63 1863.89,1268.22 1900.73,1305.06 U1.13@1900.73,1352.95
  Power Layer w7.87: v2(1849.52,1254.91) 1852.8,1254.91 1858.16,1249.56 2435.9,1249.56 2595.74,1089.72 ; 2595.78,1089.72 2610.62,1074.88 J9.5@2625,1074.88
INHC: J9.9 U1.15 | length 1041.2
  Top Layer w10: v2(1896.96,1186.98) 1898.87,1188.89 1898.87,1196.61 1902.66,1200.4 1902.66,1235.05 1940.18,1272.57 U1.15@1940.18,1352.95
  Power Layer w7.87: v2(1896.96,1186.98) 1897.66,1186.27 2313.61,1186.27 J9.9@2625,874.88
INLA: J9.3 U1.12 | length 1019.9
  Top Layer w10: v2(1818.09,1267.71) 1818.09,1269.42 1808.94,1278.57 1808.94,1335.84 1858.45,1385.35 U1.12@1875.22,1385.35
  Power Layer w7.87: v2(1818.09,1267.71) 1820.41,1270.03 1833.79,1270.03 1840.48,1276.73 1996.73,1276.73 2005.74,1267.71 2462.68,1267.71 2565.56,1164.83 2614.95,1164.83 J9.3@2625,1174.88
INLB: J9.7 U1.14 | length 1002
  Top Layer w10: v2(1879.79,1209.88) 1879.79,1239.32 1920.42,1279.95 U1.14@1920.42,1349.88
  Power Layer w7.87: v2@1877.79,1211.88 v2(1879.79,1209.88) ; v2@1880.86,1211.88 1963,1211.88 1971.51,1203.37 2396.51,1203.37 J9.7@2625,974.88
INLC: J9.11 U1.16 | length 1127.6
  Top Layer w10: v2(1886.44,1157.29) 1887.53,1158.38 1900.7,1158.38 1920.53,1178.21 1920.53,1227.65 1959.79,1266.9 U1.16@1959.79,1349.88
  Power Layer w7.87: v2(1886.44,1157.29) 2242.59,1157.29 J9.11@2625,774.88
ISENA: C36.1 J8.14 R59.1 | length 309.7
  Top Layer w15: J8.14@1025,674.88 1078.68,674.88 1090.62,662.94 1146,662.94 1146,657.04 1168.03,635.01 1168.03,629.01 1177.03,620.01 1255.44,620.01 1270.85,635.42 1270.85,662.31 R59.1@1270.22,662.94
ISENB: C49.1 J8.16 R49.1 | length 330.9
  Top Layer w15: J8.16@1025,574.88 1146,574.88 1143.81,572.69 1143.81,534.66 1152.6,525.88 1252.13,525.88 1271,544.75 R49.1@1271,574.88
ISENC: C50.1 J8.18 R63.1 | length 334.2
  Top Layer w15: J8.18@1025,474.88 1146,474.88 1146,433.03 1160.15,418.88 1245,418.88 1269.63,443.51 1269.63,474.29 R63.1@1270.22,474.88
MOTA: C12.2 C15.2 C26.1 J13.1 MOTA.1 Q1.1 Q1.2 Q1.3 Q4.5 R22.2 R37.2
  other v5: 2908,2580.88 2998,2580.88 2998,2760.88 3268,2760.88 3043,2850.88 3133,2850.88 3223,2850.88 2908,2940.88 2998,2940.88 3088,2940.88 3178,2940.88 3268,2940.88 2953,3030.88 2908,3120.88 2998,3120.88 3268,3120.88 2953,3210.88 3043,3210.88 3133,3210.88 3223,3210.88 2908,3300.88 2998,3300.88 3088,3300.88 3178,3300.88 2953,3390.88 3043,3390.88 3133,3390.88 2908,3480.88 2998,3480.88 2593,3570.88 2683,3570.88 2773,3570.88 2863,3570.88 2953,3570.88 2728,3660.88 2818,3660.88
MOTB: C13.2 C17.2 C24.1 J13.2 MOTB.1 Q2.1 Q2.2 Q2.3 Q5.5 R38.2 R60.2
  other v3: 1918,2580.88 1963,2670.88 2008,2760.88 2278,2760.88 1963,2850.88 2053,2850.88 2143,2850.88 2233,2850.88 2008,2940.88 2098,2940.88 2188,2940.88 2278,2940.88 2008,3120.88 2278,3120.88 2053,3210.88 2143,3210.88 2233,3210.88 2098,3300.88 2188,3300.88 2278,3300.88 2143,3390.88 2233,3390.88 2098,3480.88 2188,3480.88 2278,3480.88 2143,3570.88 2233,3570.88 2323,3570.88 2098,3660.88
MOTC: C19.2 C25.1 J13.3 MOTC.1 Q3.1 Q3.2 Q3.3 Q6.5 R56.2 R75.2
  other v3: 973,2670.88 1018,2760.88 1288,2760.88 1063,2850.88 1153,2850.88 1243,2850.88 1333,2850.88 1018,2940.88 1108,2940.88 1198,2940.88 1288,2940.88 1333,3030.88 1018,3120.88 1288,3120.88 1063,3210.88 1153,3210.88 1243,3210.88 1333,3210.88 1423,3210.88 1198,3300.88 1288,3300.88 1378,3300.88 1243,3390.88 1333,3390.88 1378,3480.88 1423,3570.88 1513,3570.88 1603,3570.88 1693,3570.88 1783,3570.88 1873,3570.88 1558,3660.88 1648,3660.88 1738,3660.88
Net3.3V_2: 3.3V.2 R15.2 | length 93.9
  Top Layer w20: 3.3V.2@1758.43,135.22 1760.04,136.83 1849.39,136.83 R15.2@1851,138.44
Net3.3V_EXT_1: 3.3V_EXT.1 C16.2 J7.2 U3.1 | length 406.1
  Top Layer w30: 3.3V_EXT.1@147,502.88 177,502.88 197,522.88 197,682.88 203.44,689.32 C16.2@299.57,689.32 ; C16.2@299.57,690.5 304.16,695.1 U3.1@380.26,695.1
Net5V_2: 5V.2 R12.2 | length 108.2
  Top Layer w10: R12.2@2070.18,133.71 R12.2@2071.54,135.07
  Top Layer w20: 5V.2@1963.94,133.71 R12.2@2070.18,133.71
Net5V_EXT_1: 5V_EXT.1 C58.2 J15.2 U7.1 | length 531.7
  Top Layer w30: J15.2@193,943.88 202.46,943.88 261.02,1002.44 C58.2@302.51,1002.44 313.04,1012.96 U7.1@381.45,1012.96 446.81,1012.96 557.11,1123.26 589.61,1123.26 609.61,1143.26 5V_EXT.1@609.61,1175.76
NetBUCK_EXT_1: BUCK_EXT.1 C21.1 J6.2 R19.2 U2.2 | length 649
  Top Layer w10: C21.1@466.86,2280.41 466.86,2247.93 469.11,2245.68 C21.1@480.56,2234.22 ; BUCK_EXT.1@691.44,2006.47 BUCK_EXT.1@691.44,2038.97
  Top Layer w20: U2.2@468.83,2120.69 469.11,2120.97 469.11,2181.13 R19.2@469.39,2181.41
  Top Layer w30: J6.2@464.27,2426.92 465.56,2425.63 465.56,2314.18 466.86,2312.89 C21.1@466.86,2280.41 ; C21.1@469.11,2245.68 469.11,2181.68 R19.2@469.39,2181.41 ; C21.1@480.56,2234.22 496.18,2234.22 BUCK_EXT.1@691.44,2038.97
NetC11_1: C11.1 U2.7 | length 76.8
  Top Layer w20: C11.1@462.27,1845.41 C11.1@465.02,1848.15 ; U2.7@467.02,1904.31 U2.7@468.83,1906.12 470.13,1904.81 470.13,1838.18 C11.1@471.44,1836.88
NetC11_2: C11.2 L1.1 R20.2 U2.8 | length 11.8
  Top Layer w20: L1.1@436.19,1671.71 L1.1@444.52,1663.37
NetC12_1: C12.1 R25.1 | length 63.5
  Top Layer w15: R25.1@2770.77,3230.15 C12.1@2834.25,3230.15
NetC13_1: C13.1 R26.1 | length 73
  Top Layer w15: C13.1@2358.68,3238.06 R26.1@2431.73,3238.06
NetC14_1: C14.1 R27.1 | length 81
  Top Layer w15: C14.1@1502.96,3276.09 R27.1@1583.92,3276.09
NetC15_1: C15.1 GHA.1 Q1.4 R22.1 R28.2 | length 707.7
  Top Layer w25: GHA.1@2784.21,2478.31 R22.1@2876.97,2478.31 ; R28.2@2786.81,2371.65 2783.56,2374.89 R28.2@2783.56,2375.88 2783.56,2491.86 2806.71,2515.01 v7(2806.71,2543.61) ; R22.1@2876.97,2475.7 2936.39,2475.7 2942.27,2481.58 C15.1@2945.22,2481.58 C15.1@2944.34,2482.47 ; Q1.4@2912.43,2804.89 v7(2912.43,2832.39)
  Bottom Layer w30: v7(2806.71,2543.61) 2871.42,2608.32 2871.42,2791.39 v7(2912.43,2832.39)
NetC17_1: C17.1 GHB.1 Q2.4 R29.2 R60.1 | length 756
  Top Layer w30: R29.2@1745.56,2393.94 GHB.1@1745.56,2481.85 ; v7(1793.69,2548.19) 1787.4,2541.9 1787.4,2512.51 1767.4,2492.51 GHB.1@1734.9,2492.51 GHB.1@1745.56,2481.85 ; R60.1@1868.93,2475.7 1868.18,2476.45 1750.96,2476.45 GHB.1@1745.56,2481.85 ; R60.1@1869.91,2475.7 1928.41,2475.7 1932.35,2479.64 C17.1@1934.83,2479.64 ; Q2.4@1907.04,2804.89 v7(1907.04,2833.83)
  Bottom Layer w30: v7(1793.69,2548.19) 1872.88,2627.38 1872.88,2799.66 v7(1907.04,2833.83)
NetC19_1: C19.1 GHC.1 Q3.4 R30.2 R75.1 | length 752.6
  Top Layer w10: Q3.4@920.18,2820.58 Q3.4@920.89,2821.28
  Top Layer w25: GHC.1@733,2492.51 747.37,2492.51 756.43,2483.45 GHC.1@774.57,2483.45 ; GHC.1@784.59,2515.01 v7(784.59,2543.31) ; GHC.1@785.5,2472.51 802.95,2455.06 804.28,2455.06 806.17,2453.17 C19.1@893.08,2453.17 ; C19.1@891,2455.26 892.47,2453.79 955.53,2453.79 R75.1@957,2452.32 956.46,2451.78 956.46,2395.56 R30.2@956.91,2395.11
  Top Layer w30: GHC.1@785.03,2512.04 765.5,2492.51 GHC.1@785.5,2472.51 ; Q3.4@920.89,2821.28 v7(920.89,2845.18)
  Power Layer w25: v7(784.59,2543.31) v7@785.17,2543.89
  Bottom Layer w30: v7(784.59,2543.31) 877,2635.72 877,2796.34 v7(920.89,2845.18)
NetC22_2: C22.2 C23.1 R20.1 | length 411.9
  Top Layer w20: C22.2@186,1548.44 R20.1@186,1613.26 186,1617.19 184.19,1619 168.44,1619 145,1642.44 145,1708.72 269.96,1833.67 309.51,1833.67 315.26,1839.42 C23.1@315.26,1840.41
NetC23_2: C23.2 R21.1 R24.2 U2.5 | length 209.1
  Top Layer w20: R21.1@233.39,1911.41 233.67,1911.13 283.52,1911.13 283.8,1910.85 367.02,1910.85 368.83,1909.04 U2.5@368.83,1906.12 369.1,1905.85 369.1,1837.37 C23.2@369.38,1837.09 ; C23.2@371.04,1838.75 C23.2@371.39,1838.41
NetC24_2: C24.2 R41.2 | length 73
  Top Layer w15: C24.2@2359.17,3347.68 R41.2@2432.22,3347.68
NetC25_2: C25.2 R42.2 | length 84.8
  Top Layer w15: C25.2@1498.74,3371.78 R42.2@1583.52,3371.78
NetC26_2: C26.2 R40.2 | length 55.6
  Top Layer w15: R40.2@2774.77,3340.33 C26.2@2830.39,3340.33
NetC27_1: C27.1 GLA.1 Q4.4 R34.2 R76.1 | length 726.5
  Top Layer w25: R34.2@3021.28,2284.44 R76.1@3021.28,2343.05 ; v7(3021.86,2444) 3022.12,2443.74 3022.12,2411.14 C27.1@3022.38,2410.88 R76.1@3022.38,2349.8 ; Q4.4@3212.49,2596.88 3291.64,2596.88 3363.56,2668.79 3363.56,2739.43 GLA.1@3381,2756.88
  Top Layer w30: R76.1@3019.44,2345.88 R76.1@3019.87,2345.88 ; R34.2@3019.55,2285.18 3020.3,2284.44 R34.2@3021.28,2284.44
  Power Layer w25: v7@3021.28,2439.7 3125.2,2543.61 3169.38,2543.61 3222.64,2596.88 v7(3251,2596.88)
NetC28_1: C28.1 GLB.1 Q5.4 R35.2 R77.1 | length 770.9
  Top Layer w25: R35.2@1980.44,2244.01 1980.44,2291.95 R77.1@2002.51,2314.01 2005.75,2317.26 2005.75,2347.59 2008.62,2350.46 C28.1@2008.62,2405.68 2008.85,2405.9 2008.85,2429.07 v3(2009.08,2429.3) ; Q5.4@2209,2577.88 2210.3,2579.17 2256.83,2579.17 2356.5,2678.85 2356.5,2732.39 GLB.1@2379,2754.89
  Bottom Layer w25: v3(2009.08,2429.3) 2010.03,2430.25 2010.03,2438.34 2150.87,2579.17 v2(2241.3,2579.17)
NetC29_1: C29.1 GLC.1 Q6.4 R36.2 R78.1 | length 559.2
  Top Layer w25: Q6.4@1216,2594.88 1216,2585.48 1286.42,2515.06 ; R36.2@1401.79,2480.03 1355.13,2480.03 1349.27,2474.17 C29.1@1286.42,2474.17 1286.42,2515.06 ; GLC.1@1442.25,2742.02 1425.05,2724.82 1425.05,2653.69 1286.42,2515.06
NetC31_1: C31.1 R58.1 U3.3 | length 387.7
  Top Layer w25: C31.1@286.77,511.9 U3.3@380.53,511.9 ; U3.3@381.45,512.81 386.66,507.6 403.39,507.6 425.55,485.44 R58.1@664,485.44
NetC32_1: C32.1 R9.2 U1.23 VREF_EXT.1 | length 329.5
  Top Layer w10: U1.23@2097.58,1352.95 2097.58,1327.04 2098.27,1326.36 2098.27,1315.18 2113.76,1299.69 2125.03,1299.69 2137.58,1287.13 2145.22,1287.13 ; 2145.24,1287.12 2151.08,1287.12 2157.48,1280.71 C32.1@2157.48,1278.9
  Top Layer w15: C32.1@2154,1269.88 2154,1178.52 2194.64,1137.88 VREF_EXT.1@2194.64,1070.55
NetC59_1: C59.1 R13.1 U7.3 | length 512.9
  Top Layer w10: U7.3@378.06,828.48 U7.3@381.45,831.86
  Top Layer w25: U7.3@381.45,831.86 650.69,831.86 729,753.55 R13.1@729,702.44
  Top Layer w30: C59.1@301.09,828.48 U7.3@378.06,828.48
NetF1_2: F1.2 J10.1
NetGVDD_2: GVDD.2 R17.2 | length 81.5
  Top Layer w20: GVDD.2@1329,135.22 GVDD.2@1329.61,135.83 ; GVDD.2@1342.55,133.52 1344.01,134.98 1420.54,134.98 R17.2@1422,136.44
NetJ8_1: J8.1 R6.2 | length 171.6
  Top Layer w25: R6.2@753.44,1274.88 J8.1@925,1274.88
NetJ8_2: J8.2 R7.1 | length 91.3
  Top Layer w20: J8.2@1025,1274.88 1026,1275.88 1026,1364.32 R7.1@1027,1365.32
NetJ8_7: J8.7 R8.2 | length 106.8
  Top Layer w15: R8.2@818.22,974.88 J8.7@925,974.88
NetJ9_17: J9.17 R10.2 | length 124.4
  Top Layer w15: R10.2@2500.56,474.88 J9.17@2625,474.88
NetnFAULT_2: nFAULT.2 R14.2 | length 116.1
  Top Layer w20: nFAULT.2@1541,135.22 1594.46,81.76 R14.2@1635,81.76
NetNT1_1: NT1.1 R45.2 | length 1872.1
  Top Layer w10: R45.2@1556.88,1828.84 1558.84,1828.84 1609.34,1879.34 v2(1710.79,1879.34) ; v2(2711.46,1828.59) 2892.16,1828.59 3102.95,2039.38 3102.95,2198.78 NT1.1@3126.46,2227.88
  Bottom Layer w10: v2(1710.79,1879.34) 2115.46,1879.34 2161.36,1833.44 2668.87,1833.44 2673.72,1828.59 v2(2711.46,1828.59)
NetNT2_1: NT2.1 R54.2 | length 1114.6
  Top Layer w10: v2(1413.88,1555.1) 1413.88,1517.41 R54.2@1414.13,1517.16 ; v2(2152.56,2131.22) 2153,2131.66 NT2.1@2153,2167.88
  Bottom Layer w10: v2(1413.88,1555.1) 1497.53,1638.74 1497.53,1745.22 1881.68,2129.38 2150.72,2129.38 v2(2152.56,2131.22)
NetNT3_1: NT3.1 R53.2 | length 1119.9
  Top Layer w10: v4@1166.9,2144.98 v4(1167,2144.88) NT3.1@1167,2182.88 ; v4(1445.03,1421.71) 1445.03,1419.46 1562.38,1302.11 R53.2@1636.32,1302.11
  Power Layer w10: v4(1167,2144.88) 1167,1697.49 1442.78,1421.71 v4(1445.03,1421.71)
NetNT4_1: NT4.1 R11.2 | length 1690.8
  Top Layer w10: v2(2659.39,1810.57) 2659.39,1812.4 2691.38,1844.39 2691.38,1845.61 2697.24,1851.46 2880.06,1851.46 3084.79,2056.19 NT4.1@3084.79,2246.41
  Top Layer w15: R11.2@1697.61,1828.84 1697.73,1828.72 1740,1828.72 v2(1740.13,1828.59)
  Bottom Layer w15: v2(1740.13,1828.59) 1740.38,1828.84 2137.14,1828.84 2157.92,1808.07 2655.54,1808.07 2658.04,1810.57 v2(2659.39,1810.57)
NetNT5_1: NT5.1 R32.2 | length 1037.9
  Top Layer w10: R32.2@1413.88,1598.79 R32.2@1415.85,1598.79 ; R32.2@1420.98,1609.06 v2(1443.8,1631.88) ; NT5.1@2064,2211.88 2070.22,2205.66 2070.36,2205.66 2094.92,2181.09 2094.92,2161.69 2101.65,2154.96 v2(2101.65,2152.26)
  Bottom Layer w10: v2(1443.8,1631.88) 1446.51,1631.88 1462.56,1647.93 1466.22,1647.93 1479.03,1660.75 1479.03,1754.64 1876.65,2152.26 v2(2101.65,2152.26)
NetNT6_1: NT6.1 R50.2 | length 1170.1
  Top Layer w10: NT6.1@1026.99,2311.06 1026.99,2206.52 1198.46,2035.06 v4(1200.03,2035.06) ; v4(1473.93,1426.68) 1509.47,1391.14 R50.2@1558.88,1391.14
  Power Layer w10: v4(1200.03,2035.06) 1268.92,1966.17 1268.92,1631.69 v4(1473.93,1426.68)
NetR16_2: R16.2 VMOTOR_LED.2 | length 92
  Top Layer w15: R16.2@190.85,2105.38 VMOTOR_LED.2@190.85,2197.41
NetR19_1: R19.1 R57.2 U2.3 | length 173.8
  Top Layer w20: R57.2@384.56,2280.88 384.56,2279.89 390.31,2274.15 391.29,2274.15 414.27,2251.17 R19.1@414.27,2181.41 ; R19.1@417.02,2181.41 417.02,2122.5 U2.3@418.83,2120.69
NetR23_2: R23.2 U2.4 | length 61
  Top Layer w20: U2.4@368.83,2120.69 R23.2@368.83,2181.72
NetU1_31: U1.31
nFAULT: J8.19 R4.2 R14.1 U1.22 | length 2297.5
  Top Layer w8: J8.19@925,374.88 925,284.88 v2(939,270.88) ; R14.1@1635,136.88 v2(1635,210.88) 1635.93,211.81 1635.93,628.08 v2(1636.87,629.01)
  Top Layer w10: v2(2022.24,1070.87) 2023.27,1071.9 2023.27,1085.51 2023.01,1085.77 2023.01,1132.37 2040.88,1150.24 2040.88,1151.22 2051.63,1161.97 R4.2@2052.61,1161.97 ; R4.2@2053.41,1161.78 2077.9,1186.27 U1.22@2077.9,1349.88
  Power Layer w8: v2(939,270.88) 999,210.88 v2(1635,210.88) ; v2(1636.87,629.01) 1636.87,803.2 1717.85,884.18 1836.87,884.18 2022.24,1069.55 v2(2022.24,1070.87)
nSCS: J9.4 U1.20 | length 1229.9
  Top Layer w10: v2(1991.14,1007.51) 1992.03,1008.4 1992.03,1194.54 2038.33,1240.84 2038.33,1359.48 U1.20@2038.61,1359.76
  Bottom Layer w8: v2(1991.14,1007.51) 1991.14,1006.1 2054.9,942.33 2379.64,942.33 2561.39,1124.07 2634.13,1124.07 2682.49,1172.42 2722.55,1172.42 J9.4@2725,1174.88
nSLEEP: J8.17 U1.21 | length 1769
  Top Layer w8: J8.17@925,474.88 971,520.88 v2(1088,520.88)
  Top Layer w10: v2(2055.01,1225.18) 2056.92,1227.09 2056.92,1234.17 2058.21,1235.46 U1.21@2058.21,1349.88
  Power Layer w8: v2(1479.73,1080.78) 1479.73,1175.97 1534.96,1231.19 1860.43,1231.19 1860.99,1231.75 1965.49,1231.75 1972.06,1225.18 v2(2055.01,1225.18)
  Power Layer w10: v2(1088,520.88) 1207.19,640.07 1279.61,640.07 v2(1479.03,839.49)
  Bottom Layer w10: v2(1479.03,839.49) 1479.38,839.84 1479.38,1080.44 v2(1479.73,1080.78)
SCLK: J8.13 U1.19 | length 1545.9
  Top Layer w8: U1.19@2018.28,1349.31 U1.19@2018.84,1349.88
  Top Layer w10: v2(1969.16,1084.97) 1969.16,1119.76 1974.16,1124.76 1974.16,1205.44 2018.28,1249.56 U1.19@2018.28,1349.31
  Power Layer w8: J8.13@925,674.88 973.39,723.27 1033.33,723.27 1119.2,809.13 1119.2,815.64 1205.06,901.5 v2(1205.07,937.48)
  Bottom Layer w8: v2(1205.07,937.48) 1205.53,937.48 1378.93,1110.88 1940.4,1110.88 1966.31,1084.97 v2(1969.16,1084.97)
SDI: J9.12 U1.18 | length 1243.9
  Top Layer w10: v2(1931.01,1086.82) 1932.92,1088.74 1932.92,1109.76 1956.28,1133.12 1956.28,1212.84 1999.16,1255.72 U1.18@1999.16,1348.88
  Bottom Layer w10: v2(1931.01,1086.82) 1930.69,1086.51 1930.69,1035.61 2144.66,821.64 2678.24,821.64 J9.12@2725,774.88
SDO: J9.14 U1.17 | length 1362
  Top Layer w10: v2(1879.32,1065.66) 1899.51,1085.84 1899.51,1101.62 1938.41,1140.53 1938.41,1220.25 1979.47,1261.31 U1.17@1979.47,1348.88
  Bottom Layer w10: v2(1879.32,1065.66) 1879.32,1062.95 1886.44,1055.83 1886.44,1006.71 2174.89,718.26 2625,718.26 cw(c2625,674.88) 2638.23,716.2 2683.68,716.2 2686.61,713.27 J9.14@2725,674.88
